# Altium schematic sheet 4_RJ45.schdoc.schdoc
size 431 x 309 mm; Symbol: Sheet-Symbol_A3; Device: Sheet-Symbol_A3; Company: 嘉立创EDA; Version: V1.0; Page Size: A3; @Project Name: RTL8367S_RTL8213B; @Page Count: 5; @Update Date: 2022-12-13; @Create Date: 2022-10-17; @Schematic Name: Schematic1; @Page No: 4; @Page Name: RJ45
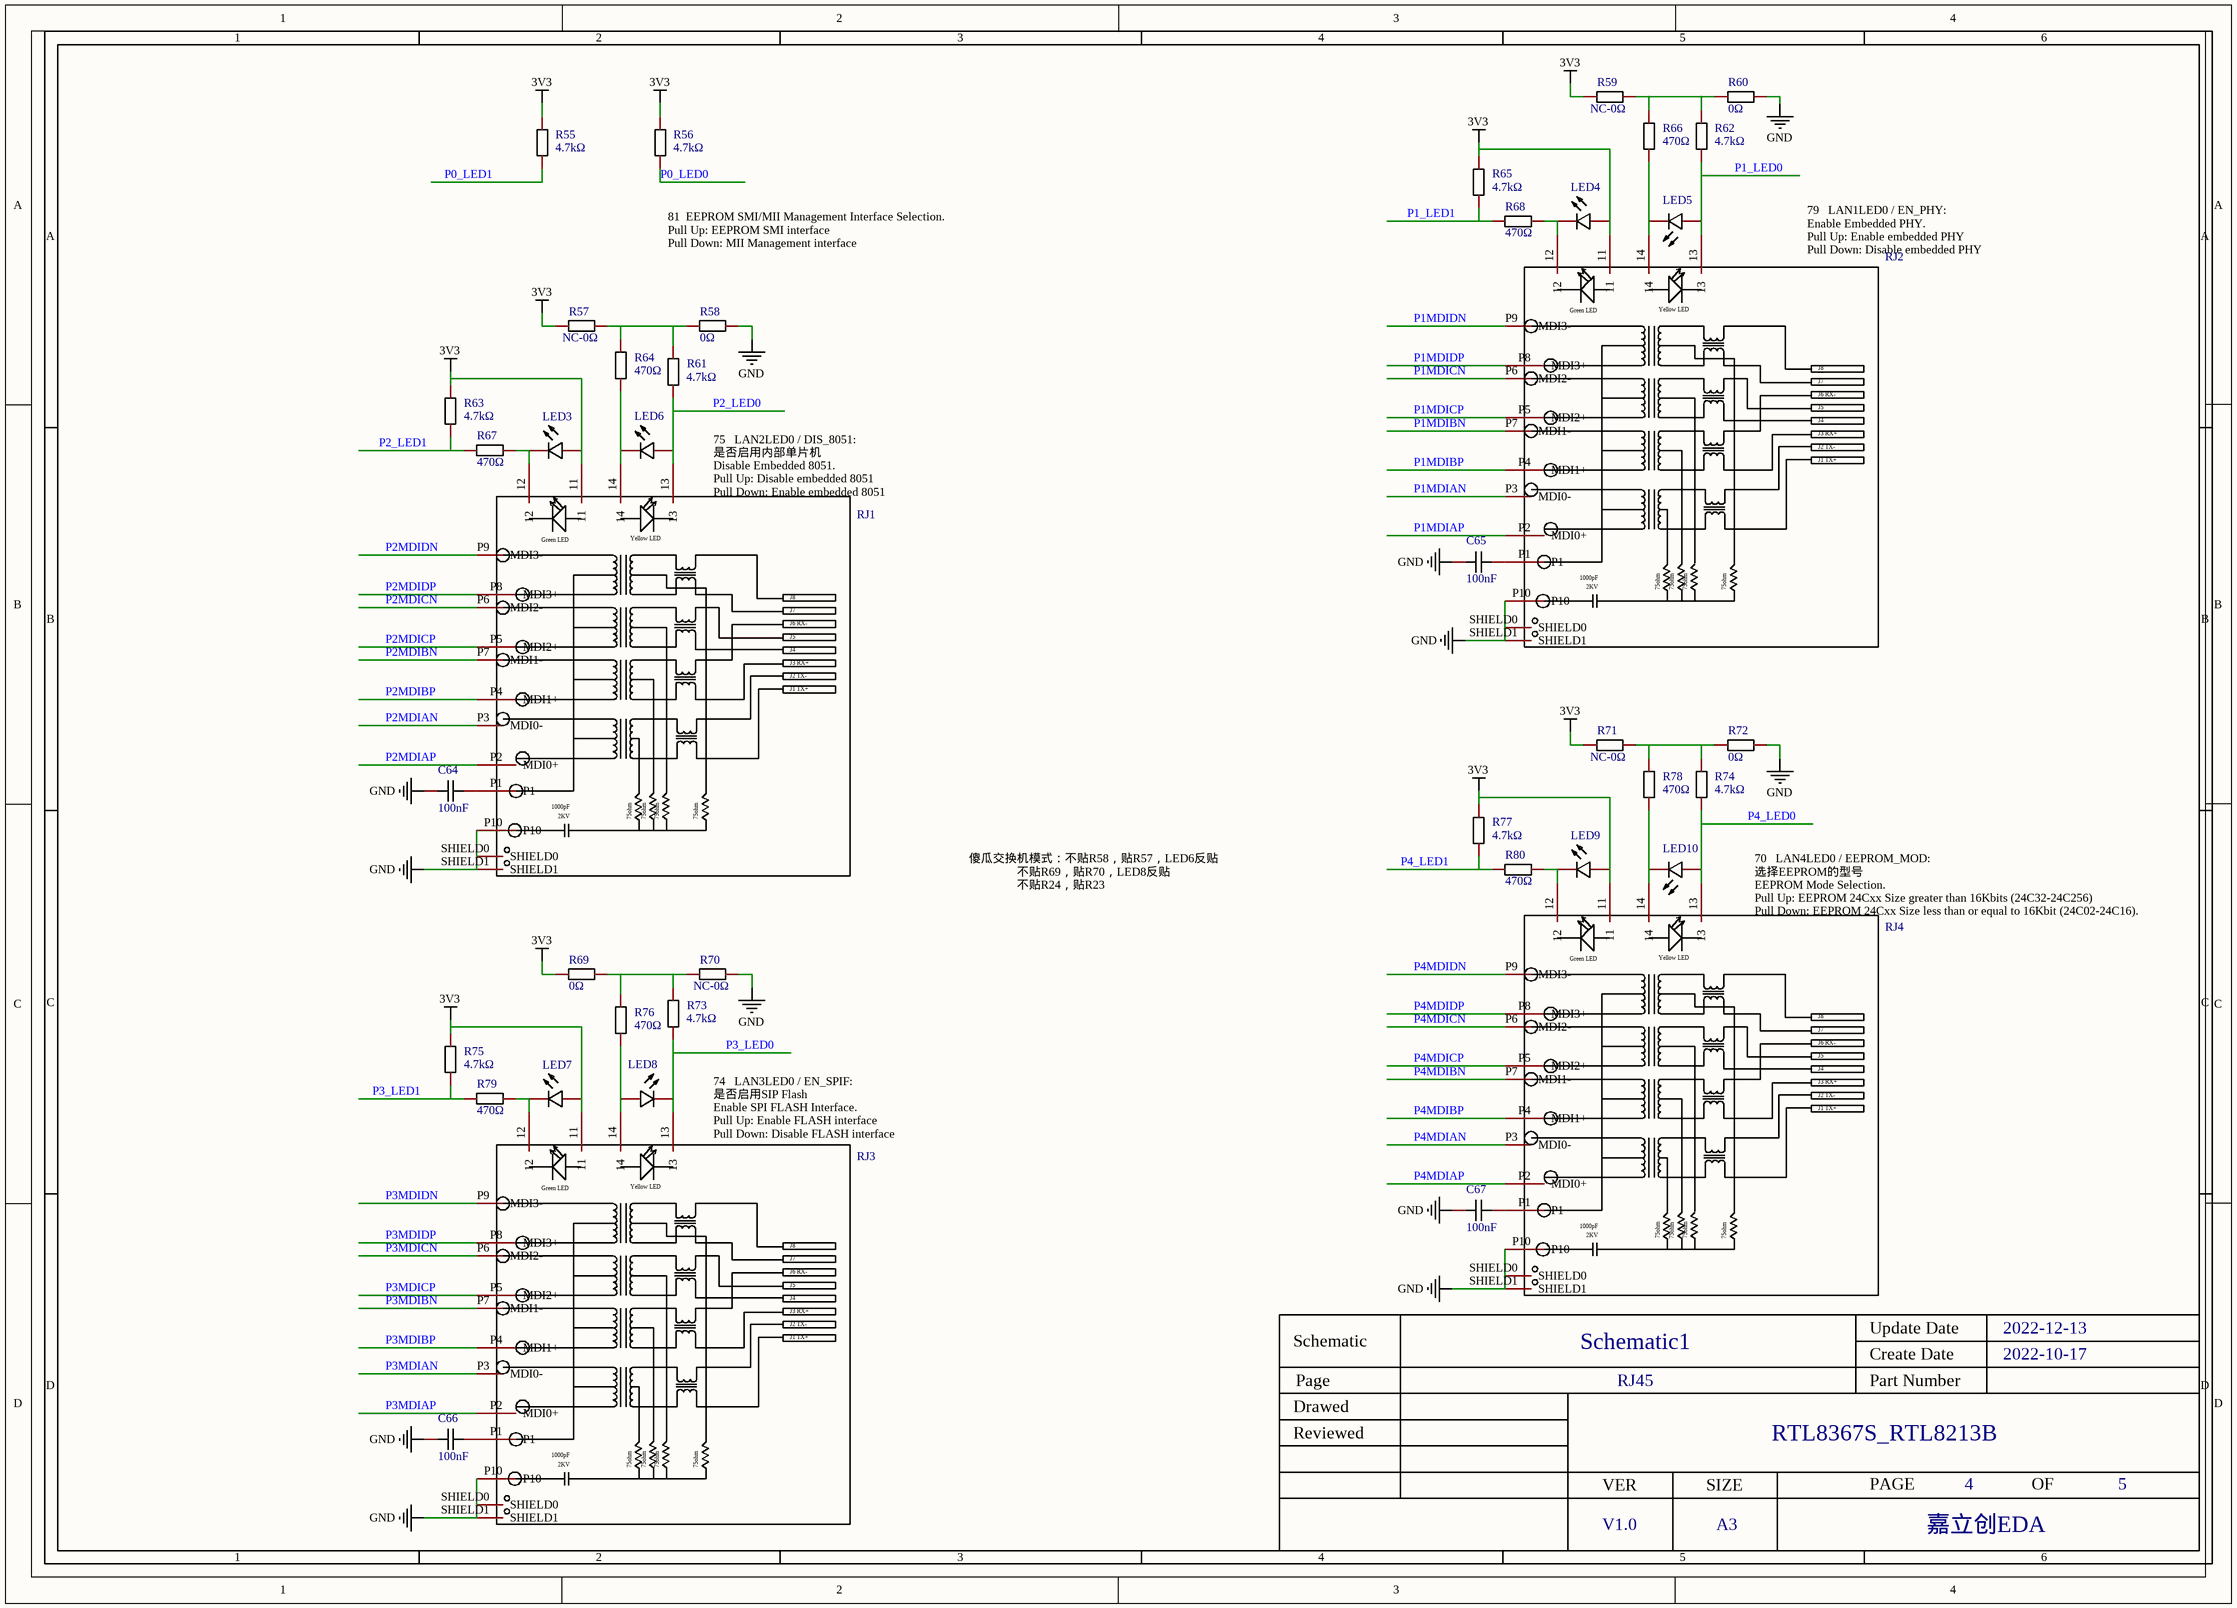
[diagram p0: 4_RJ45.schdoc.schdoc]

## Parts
C64  100nF  [C0402]
C65  100nF  [C0402]
C66  100nF  [C0402]
C67  100nF  [C0402]
LED3  19-213/Y2C-CQ2R2L/3T(CY)  [LED0603-R-RD]  (value not drawn)
LED4  19-213/Y2C-CQ2R2L/3T(CY)  [LED0603-R-RD]  (value not drawn)
LED5  19-217/GHC-YR1S2/3T  [LED0603-R-RD]  (value not drawn)
LED6  19-217/GHC-YR1S2/3T  [LED0603-R-RD]  (value not drawn)
LED7  19-213/Y2C-CQ2R2L/3T(CY)  [LED0603-R-RD]  (value not drawn)
LED8  19-217/GHC-YR1S2/3T  [LED0603-R-RD]  (value not drawn)
LED9  19-213/Y2C-CQ2R2L/3T(CY)  [LED0603-R-RD]  (value not drawn)
LED10  19-217/GHC-YR1S2/3T  [LED0603-R-RD]  (value not drawn)
R55  value 4.7kΩ  [R0402]  (hidden comment: 0402WGF4701TCE)
R56  value 4.7kΩ  [R0402]  (hidden comment: 0402WGF4701TCE)
R57  value NC-0Ω  [R0402]  (hidden comment: 0402WGF0000TCE)
R58  value 0Ω  [R0402]  (hidden comment: 0402WGF0000TCE)
R59  value NC-0Ω  [R0402]  (hidden comment: 0402WGF0000TCE)
R60  value 0Ω  [R0402]  (hidden comment: 0402WGF0000TCE)
R61  value 4.7kΩ  [R0402]  (hidden comment: 0402WGF4701TCE)
R62  value 4.7kΩ  [R0402]  (hidden comment: 0402WGF4701TCE)
R63  value 4.7kΩ  [R0402]  (hidden comment: 0402WGF4701TCE)
R64  value 470Ω  [R0402]  (hidden comment: 0402WGF4700TCE)
R65  value 4.7kΩ  [R0402]  (hidden comment: 0402WGF4701TCE)
R66  value 470Ω  [R0402]  (hidden comment: 0402WGF4700TCE)
R67  value 470Ω  [R0402]  (hidden comment: 0402WGF4700TCE)
R68  value 470Ω  [R0402]  (hidden comment: 0402WGF4700TCE)
R69  value 0Ω  [R0402]  (hidden comment: 0402WGF0000TCE)
R70  value NC-0Ω  [R0402]  (hidden comment: 0402WGF0000TCE)
R71  value NC-0Ω  [R0402]  (hidden comment: 0402WGF0000TCE)
R72  value 0Ω  [R0402]  (hidden comment: 0402WGF0000TCE)
R73  value 4.7kΩ  [R0402]  (hidden comment: 0402WGF4701TCE)
R74  value 4.7kΩ  [R0402]  (hidden comment: 0402WGF4701TCE)
R75  value 4.7kΩ  [R0402]  (hidden comment: 0402WGF4701TCE)
R76  value 470Ω  [R0402]  (hidden comment: 0402WGF4700TCE)
R77  value 4.7kΩ  [R0402]  (hidden comment: 0402WGF4701TCE)
R78  value 470Ω  [R0402]  (hidden comment: 0402WGF4700TCE)
R79  value 470Ω  [R0402]  (hidden comment: 0402WGF4700TCE)
R80  value 470Ω  [R0402]  (hidden comment: 0402WGF4700TCE)
RJ1  hr911130a  [rj45-th_hr911130a]  (value not drawn)
RJ2  hr911130a  [rj45-th_hr911130a]  (value not drawn)
RJ3  hr911130a  [rj45-th_hr911130a]  (value not drawn)
RJ4  hr911130a  [rj45-th_hr911130a]  (value not drawn)

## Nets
3V3: LED3.1(A) LED4.1(A) LED7.1(A) LED9.1(A) R55.1 R56.1 R57.1 R59.1 R63.1 R65.1 R69.1 R71.1 R75.1 R77.1 RJ1.11 RJ2.11 RJ3.11 RJ4.11
GND: C64.1 C65.1 C66.1 C67.1 R58.1 R60.1 R70.1 R72.1 RJ1.P10 RJ1.SHIELD0 RJ1.SHIELD1 RJ2.P10 RJ2.SHIELD0 RJ2.SHIELD1 RJ3.P10 RJ3.SHIELD0 RJ3.SHIELD1 RJ4.P10 RJ4.SHIELD0 RJ4.SHIELD1
P0_LED0: R56.2
P0_LED1: R55.2
P1_LED0: LED5.1(A) R62.2 RJ2.13
P1_LED1: R65.2 R68.2
P1MDIAN: RJ2.P3(MDI0-)
P1MDIAP: RJ2.P2(MDI0+)
P1MDIBN: RJ2.P7(MDI1-)
P1MDIBP: RJ2.P4(MDI1+)
P1MDICN: RJ2.P6(MDI2-)
P1MDICP: RJ2.P5(MDI2+)
P1MDIDN: RJ2.P9(MDI3-)
P1MDIDP: RJ2.P8(MDI3+)
P2_LED0: LED6.1(A) R61.2 RJ1.13
P2_LED1: R63.2 R67.2
P2MDIAN: RJ1.P3(MDI0-)
P2MDIAP: RJ1.P2(MDI0+)
P2MDIBN: RJ1.P7(MDI1-)
P2MDIBP: RJ1.P4(MDI1+)
P2MDICN: RJ1.P6(MDI2-)
P2MDICP: RJ1.P5(MDI2+)
P2MDIDN: RJ1.P9(MDI3-)
P2MDIDP: RJ1.P8(MDI3+)
P3_LED0: LED8.2(K) R73.2 RJ3.13
P3_LED1: R75.2 R79.2
P3MDIAN: RJ3.P3(MDI0-)
P3MDIAP: RJ3.P2(MDI0+)
P3MDIBN: RJ3.P7(MDI1-)
P3MDIBP: RJ3.P4(MDI1+)
P3MDICN: RJ3.P6(MDI2-)
P3MDICP: RJ3.P5(MDI2+)
P3MDIDN: RJ3.P9(MDI3-)
P3MDIDP: RJ3.P8(MDI3+)
P4_LED0: LED10.1(A) R74.2 RJ4.13
P4_LED1: R77.2 R80.2
P4MDIAN: RJ4.P3(MDI0-)
P4MDIAP: RJ4.P2(MDI0+)
P4MDIBN: RJ4.P7(MDI1-)
P4MDIBP: RJ4.P4(MDI1+)
P4MDICN: RJ4.P6(MDI2-)
P4MDICP: RJ4.P5(MDI2+)
P4MDIDN: RJ4.P9(MDI3-)
P4MDIDP: RJ4.P8(MDI3+)
NetC64_2: C64.2 RJ1.P1
NetC65_2: C65.2 RJ2.P1
NetC66_2: C66.2 RJ3.P1
NetC67_2: C67.2 RJ4.P1
NetLED3_2: LED3.2(K) R67.1 RJ1.12
NetLED4_2: LED4.2(K) R68.1 RJ2.12
NetLED5_2: LED5.2(K) R66.2 RJ2.14
NetLED6_2: LED6.2(K) R64.2 RJ1.14
NetLED7_2: LED7.2(K) R79.1 RJ3.12
NetLED8_1: LED8.1(A) R76.2 RJ3.14
NetLED9_2: LED9.2(K) R80.1 RJ4.12
NetLED10_2: LED10.2(K) R78.2 RJ4.14
NetR57_2: R57.2 R58.2 R61.1 R64.1
NetR59_2: R59.2 R60.2 R62.1 R66.1
NetR69_2: R69.2 R70.2 R73.1 R76.1
NetR71_2: R71.2 R72.2 R74.1 R78.1

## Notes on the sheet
- (near R58) 81  EEPROM SMI/MII Management Interface Selection.
  Pull Up: EEPROM SMI interface
  Pull Down: MII Management interface
- 79   LAN1LED0 / EN_PHY:
  Enable Embedded PHY.
  Pull Up: Enable embedded PHY
  Pull Down: Disable embedded PHY
- 75   LAN2LED0 / DIS_8051:
  是否启用内部单片机
  Disable Embedded 8051.
  Pull Up: Disable embedded 8051
  Pull Down: Enable embedded 8051
- 傻瓜交换机模式：不贴R58，贴R57，LED6反贴
  不贴R69，贴R70，LED8反贴
  不贴R24，贴R23
- 70   LAN4LED0 / EEPROM_MOD:
  选择EEPROM的型号
  EEPROM Mode Selection.
  Pull Up: EEPROM 24Cxx Size greater than 16Kbits (24C32-24C256)
  Pull Down: EEPROM 24Cxx Size less than or equal to 16Kbit (24C02-24C16).
- 74   LAN3LED0 / EN_SPIF:
  是否启用SIP Flash
  Enable SPI FLASH Interface.
  Pull Up: Enable FLASH interface
  Pull Down: Disable FLASH interface

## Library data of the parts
C64-C67 = CL05B104KB54PNC: Manufacturer: SAMSUNG(三星); Symbol: fn15x104k250png; Add into BOM: yes; Tolerance: ±10%; Voltage Rated: 50V; Temperature Coefficient: X7R; Description: 容值:100nF;精度:±10%;额定电压:50V;材质(温度系数):X7R;
LED3 LED4 LED7 LED9 = 19-213/Y2C-CQ2R2L/3T(CY): 发光颜色:红灯;; Manufacturer: EVERLIGHT(亿光); Symbol: FC-DA1608HRK-620D; Add into BOM: yes; Illumination Color: 黄色; Luminous Intensity (IF=20mA): 90~180mcd; Dominant Wavelength / Coordinate rank: 585.5~591.5nm; Emitted Color: 红灯
LED5 LED6 LED8 LED10 = 19-217/GHC-YR1S2/3T: 发光颜色:红灯;; Manufacturer: EVERLIGHT(亿光); Symbol: FC-DA1608HRK-620D; Add into BOM: yes; Emitted Color: 翠绿; Lens Color: 无色透明; Dominant Wavelength: 520nm~535nm; Peak Wavelength: 518nm; Forward Current: 20mA; Power Dissipation: 110mW; Viewing Angle: 120°
R55 R56 R61-R63 R65 R73-R75 R77 = 0402WGF4701TCE: 电阻类型:薄膜电阻;阻值:10kΩ;精度:±0.5%;功率:63mW;温度系数:±25ppm/;最大工作电压:25V;工作温度范围:-55~+155;; Manufacturer: UNI-ROYAL(厚声); Symbol: tr0402d10kq1025; Add into BOM: yes; Tolerance: ±1%; Power(Watts): 1/16W; Temperature Coefficient: ±100ppm/℃; Overload Voltage (Max): 50V
R57 R59 R70 R71 = 0402WGF0000TCE: 电阻类型:薄膜电阻;阻值:10kΩ;精度:±0.5%;功率:63mW;温度系数:±25ppm/;最大工作电压:25V;工作温度范围:-55~+155;; Manufacturer: UNI-ROYAL(厚声); Symbol: tr0402d10kq1025; Add into BOM: no; Convert to PCB: yes; Tolerance: ±1%; Power(Watts): 1/16W; Temperature Coefficient: ±800ppm/℃; Overload Voltage (Max): 50V
R58 R60 R69 R72 = 0402WGF0000TCE: 电阻类型:薄膜电阻;阻值:10kΩ;精度:±0.5%;功率:63mW;温度系数:±25ppm/;最大工作电压:25V;工作温度范围:-55~+155;; Manufacturer: UNI-ROYAL(厚声); Symbol: tr0402d10kq1025; Add into BOM: yes; Tolerance: ±1%; Power(Watts): 1/16W; Temperature Coefficient: ±800ppm/℃; Overload Voltage (Max): 50V
R64 R66-R68 R76 R78-R80 = 0402WGF4700TCE: 电阻类型:薄膜电阻;阻值:10kΩ;精度:±0.5%;功率:63mW;温度系数:±25ppm/;最大工作电压:25V;工作温度范围:-55~+155;; Manufacturer: UNI-ROYAL(厚声); Symbol: tr0402d10kq1025; Add into BOM: yes; Tolerance: ±0.5%; Power(Watts): 63mW; Overload Voltage (Max): 25V; Temperature Coefficient: ±25ppm/
RJ1-RJ4 = hr911130a: Manufacturer: HANRUN(汉仁); Add into BOM: no; Convert to PCB: yes; Connector Type: RJ插座; USOC Codes: RJ45; Number of Ports: 1; LED: 有; Description: 连接器类型:RJ插座;USOC代码:RJ45;端口数量:1;等级:-;屏蔽:-;LED:有;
